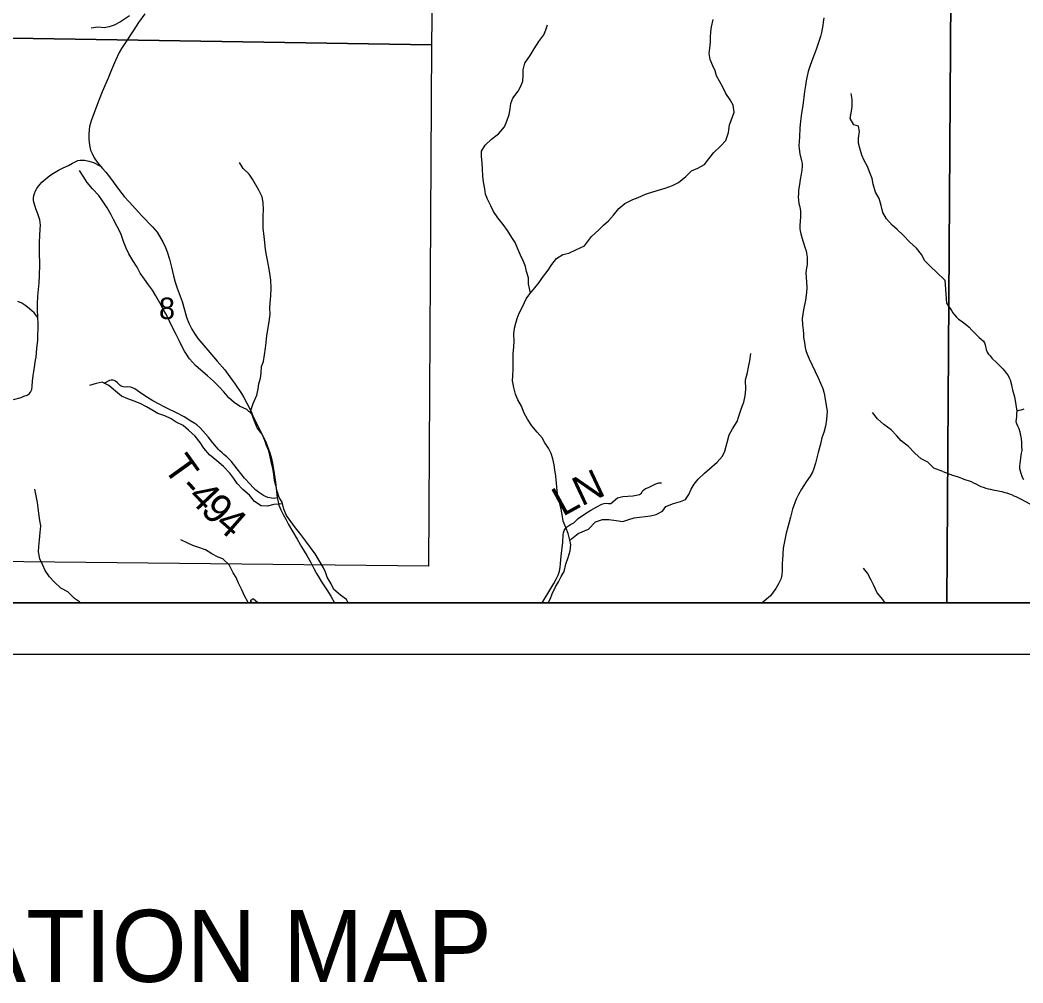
# Model space of a CAD drawing. Extents: x 0 to 34, y -8.9 to 22.
# Drawn here: x 26.904 to 28.852, y 6.366 to 8.236 of the extents above; entities that cross this region are included whole.
import ezdxf

# ---------------------------------------------------------------- set-up
doc = ezdxf.new("R2010")
doc.units = 0
for name, color, linetype in [('GM_X_Corporation', 7, 'Continuous'), ('GM_X_County_Road', 7, 'Continuous'), ('GM_X_Minor_River', 7, 'Continuous'), ('GM_X_Section_Text', 7, 'Continuous'), ('GM_X_Township_Road', 7, 'Continuous'), ('GM_X_Township_Road_Text', 7, 'Continuous'), ('SH_Data', 7, 'Continuous'), ('SH_Text', 7, 'Continuous')]:
    doc.layers.add(name, color=color, linetype=linetype)

msp = doc.modelspace()

# ---------------------------------------------------------------- linework, layer by layer
at = {"layer": 'GM_X_Corporation'}
for points in [[(28.7046, 7.104), (30.5167, 7.104), (30.5167, 13.904), (28.8143, 13.904), (28.8122, 13.7561), (28.8049, 13.053), (28.7787, 12.0377), (28.7786, 12.0342), (28.7779, 11.9899), (28.7762, 11.8872), (28.7797, 11.7437), (28.7775, 11.7346), (28.7754, 11.6346), (28.7651, 11.3014), (28.7622, 11.1187), (28.7609, 11.0119), (28.7377, 10.2012), (28.7308, 9.4444), (28.7238, 9.1729), (28.7123, 8.2818)], [(28.7046, 7.104), (30.5167, 7.104), (30.5167, 12.0118), (29.364, 12.0313), (29.2718, 12.0324), (28.9225, 12.0359), (28.8128, 12.0371), (28.7787, 12.0377), (28.7786, 12.0342), (28.7779, 11.9899), (28.7762, 11.8872), (28.7797, 11.7437), (28.7775, 11.7346), (28.7754, 11.6346), (28.7651, 11.3014), (28.7622, 11.1187), (28.7609, 11.0119), (28.7377, 10.2012), (28.7308, 9.4444), (28.7238, 9.1729), (28.7123, 8.2818)], [(27.7161, 9.2151), (27.7031, 8.1879), (26.6846, 8.2041), (26.7025, 9.2378)], [(26.6846, 8.2041), (27.7031, 8.1879), (27.6975, 7.1757), (26.6684, 7.1864)]]:
    msp.add_lwpolyline(points, close=True, dxfattribs=at)
for points in [[(23.7167, 11.9654), (23.7167, 7.104), (28.7046, 7.104), (28.7123, 8.2818), (28.7238, 9.1729), (28.7308, 9.4444), (28.7377, 10.2012)], [(24.1844, 10.755), (24.1596, 9.2636), (24.0743, 9.2644), (23.7167, 9.2682), (23.7167, 7.104), (28.7046, 7.104), (28.7123, 8.2818), (28.7238, 9.1729), (28.7308, 9.4444), (28.7377, 10.2012)]]:
    msp.add_lwpolyline(points, dxfattribs=at)
at = {"layer": 'GM_X_County_Road'}
for points in [[(27.1466, 8.2479), (27.1339, 8.2311), (27.1249, 8.2171), (27.1072, 8.1902), (27.1011, 8.1806), (27.0967, 8.1727), (27.0892, 8.1574), (27.0814, 8.1396), (27.075, 8.1233), (27.0637, 8.0969), (27.0578, 8.0819), (27.0427, 8.0422), (27.0405, 8.0358), (27.0389, 8.0296), (27.0379, 8.0229), (27.0374, 8.0145), (27.0373, 8.0044), (27.0388, 7.993), (27.0409, 7.9835), (27.0438, 7.9767), (27.0478, 7.9683), (27.0536, 7.9602), (27.0602, 7.9523)], [(27.0602, 7.9523), (27.0643, 7.9477), (27.0708, 7.9404), (27.078, 7.9316), (27.0974, 7.905), (27.1064, 7.8933), (27.1159, 7.8829), (27.1408, 7.8558), (27.1614, 7.8345), (27.1702, 7.8238), (27.1776, 7.8121), (27.1812, 7.805), (27.1864, 7.7946), (27.1899, 7.7857), (27.1944, 7.7715), (27.1981, 7.7558), (27.2018, 7.7396), (27.2056, 7.7269), (27.2093, 7.7155), (27.219, 7.6893), (27.2235, 7.6735), (27.2274, 7.6589), (27.2318, 7.6476), (27.2379, 7.6357), (27.244, 7.6251), (27.2495, 7.6175), (27.2687, 7.5946), (27.2869, 7.5736), (27.3021, 7.5564), (27.3117, 7.5433), (27.3219, 7.5288), (27.3339, 7.511), (27.3387, 7.5029), (27.3446, 7.4918), (27.3527, 7.4758), (27.3575, 7.4643), (27.3764, 7.4272), (27.3821, 7.4152), (27.3849, 7.4078), (27.3892, 7.3956), (27.3922, 7.3848), (27.3945, 7.3752), (27.3979, 7.3554), (27.4002, 7.3386), (27.4015, 7.3261), (27.4023, 7.3197), (27.4028, 7.3155), (27.4036, 7.3079), (27.4051, 7.3006), (27.407, 7.2942), (27.4107, 7.285), (27.4152, 7.2758), (27.4203, 7.2664), (27.4258, 7.2566), (27.4423, 7.2279), (27.4508, 7.2132), (27.461, 7.1961), (27.4689, 7.1824), (27.4748, 7.1712), (27.48, 7.161), (27.4852, 7.1525), (27.4899, 7.1451), (27.5002, 7.1294), (27.5079, 7.1173), (27.5151, 7.104)]]:
    msp.add_lwpolyline(points, dxfattribs=at)
at = {"layer": 'GM_X_Minor_River'}
for points in [[(27.1164, 8.2441), (27.0993, 8.2323), (27.0868, 8.2262), (27.077, 8.2231), (27.0671, 8.2212), (27.055, 8.2223), (27.0421, 8.2203)], [(27.8956, 7.7053), (27.892, 7.7239), (27.8916, 7.7357), (27.8878, 7.7478), (27.8862, 7.7573), (27.8824, 7.7668), (27.8763, 7.7796), (27.8706, 7.7929), (27.8656, 7.8039), (27.8592, 7.8138), (27.8512, 7.827), (27.8424, 7.8391), (27.8321, 7.852), (27.8241, 7.8645), (27.8184, 7.8755), (27.8119, 7.888), (27.8085, 7.8979), (27.807, 7.9081), (27.8043, 7.9221), (27.8031, 7.9328), (27.8023, 7.9472), (27.8019, 7.9578), (27.8004, 7.9719), (27.8007, 7.9813), (27.8075, 7.9931), (27.82, 8.0046), (27.8337, 8.0152), (27.845, 8.0289), (27.8499, 8.0396), (27.8541, 8.0525), (27.8563, 8.0639), (27.8578, 8.0738), (27.8612, 8.0844), (27.8718, 8.0981), (27.8767, 8.1076), (27.8805, 8.1171), (27.8816, 8.1285), (27.8812, 8.1395), (27.8846, 8.1524), (27.8948, 8.1669), (27.9031, 8.1802), (27.9118, 8.1943), (27.9213, 8.2072), (27.9254, 8.2171), (27.9285, 8.2266)], [(28.0005, 7.7978), (28.0145, 7.8159), (28.0276, 7.8278), (28.0377, 7.8374), (28.0474, 7.8462), (28.0571, 7.8574), (28.0675, 7.87), (28.0788, 7.8796), (28.0942, 7.8874), (28.1051, 7.8913), (28.119, 7.8979), (28.1333, 7.9027), (28.1465, 7.9062), (28.1571, 7.9094), (28.1718, 7.9145), (28.1834, 7.9207), (28.1973, 7.9319), (28.2085, 7.943), (28.2209, 7.9481), (28.234, 7.9555), (28.2422, 7.9666), (28.2519, 7.9788), (28.2654, 7.9915), (28.2754, 8.0023), (28.2802, 8.0175), (28.2823, 8.0323), (28.2874, 8.0464), (28.2914, 8.057), (28.2897, 8.071), (28.2835, 8.0812), (28.2755, 8.0936), (28.27, 8.1041), (28.2627, 8.1173), (28.2573, 8.1275), (28.2545, 8.1373), (28.2498, 8.1471), (28.2448, 8.1596), (28.2431, 8.1713), (28.2441, 8.1815), (28.2455, 8.1929), (28.2454, 8.2028), (28.246, 8.2134), (28.2474, 8.2229), (28.2506, 8.237)], [(28.7008, 7.7309), (28.6848, 7.7466), (28.6729, 7.7575), (28.6618, 7.7687), (28.6556, 7.7807), (28.6457, 7.7927), (28.6323, 7.8051), (28.62, 7.8182), (28.6078, 7.829), (28.5982, 7.8376), (28.5875, 7.85), (28.5801, 7.862), (28.5769, 7.876), (28.5734, 7.8896), (28.566, 7.9017), (28.5617, 7.9172), (28.5593, 7.9281), (28.5557, 7.9379), (28.5503, 7.9519), (28.5437, 7.9632), (28.5394, 7.9737), (28.5355, 7.9873), (28.5331, 7.9972), (28.533, 8.0066), (28.5351, 8.0199), (28.5331, 8.0297), (28.5236, 8.0327), (28.517, 8.0451), (28.5191, 8.0588), (28.5205, 8.0683), (28.5207, 8.0815), (28.5187, 8.0936)], [(27.351, 7.4738), (27.3571, 7.4914), (27.3639, 7.5074), (27.3665, 7.5199), (27.368, 7.5294), (27.3714, 7.5408), (27.3721, 7.5503), (27.3729, 7.5632), (27.3766, 7.5731), (27.3789, 7.586), (27.3811, 7.5985), (27.3823, 7.6095), (27.3837, 7.6232), (27.3882, 7.6498), (27.3897, 7.665), (27.3893, 7.6764), (27.3901, 7.6859), (27.3912, 7.7007), (27.3915, 7.7155), (27.3911, 7.731), (27.3892, 7.7443), (27.3865, 7.7591), (27.3846, 7.7694), (27.383, 7.7792), (27.3807, 7.7906), (27.3792, 7.8043), (27.3784, 7.8156), (27.3761, 7.8316), (27.3761, 7.8414), (27.3764, 7.8559), (27.3771, 7.8676), (27.376, 7.8817), (27.3744, 7.8927), (27.3679, 7.9059), (27.3554, 7.9268), (27.3493, 7.937), (27.3375, 7.9476), (27.3303, 7.9597)], [(27.1155, 7.7818), (27.1102, 7.7928), (27.1052, 7.806), (27.0995, 7.8212), (27.0926, 7.8352), (27.0854, 7.8485), (27.0808, 7.858), (27.0732, 7.8716), (27.0644, 7.8849), (27.0568, 7.8951), (27.0446, 7.9083), (27.034, 7.9204), (27.0268, 7.9326), (27.0191, 7.9439)], [(27.9299, 7.104), (27.9347, 7.1125), (27.9377, 7.122), (27.9441, 7.1353), (27.9502, 7.1449), (27.9551, 7.1555), (27.9611, 7.165), (27.9641, 7.1791), (27.9687, 7.1924), (27.9728, 7.2053), (27.9739, 7.2167), (27.972, 7.2262), (27.9686, 7.2387), (27.9644, 7.2504), (27.9594, 7.2629), (27.9575, 7.2758), (27.9544, 7.2895), (27.9521, 7.299), (27.9494, 7.3084), (27.9475, 7.3217), (27.9463, 7.3365), (27.9452, 7.3502), (27.9432, 7.3627), (27.9417, 7.3722), (27.939, 7.3839), (27.9356, 7.3942), (27.9306, 7.4044), (27.9238, 7.415), (27.9181, 7.4245), (27.9086, 7.4359), (27.8983, 7.448), (27.8899, 7.4612), (27.8834, 7.4726), (27.8781, 7.4862), (27.8712, 7.4987), (27.8667, 7.5097), (27.8632, 7.5226), (27.8609, 7.5352), (27.8613, 7.545), (27.862, 7.5579), (27.862, 7.5735), (27.8623, 7.5879), (27.863, 7.6016), (27.8638, 7.6126), (27.8634, 7.6266), (27.8645, 7.6376), (27.8675, 7.6471), (27.8697, 7.6566), (27.8735, 7.6665), (27.8811, 7.6802), (27.8875, 7.6943), (27.8947, 7.7042), (27.9041, 7.716), (27.9125, 7.7266), (27.9189, 7.7361), (27.9303, 7.7502), (27.9374, 7.7612), (27.9465, 7.7727), (27.9583, 7.7807), (27.9704, 7.783), (27.9837, 7.7899), (28.0005, 7.7978)], [(27.5414, 7.104), (27.5385, 7.1105), (27.5268, 7.1192), (27.5138, 7.1298), (27.5081, 7.1412), (27.5005, 7.154), (27.4974, 7.1639), (27.4929, 7.1734), (27.4853, 7.1863), (27.4776, 7.1995), (27.4685, 7.212), (27.4594, 7.2238), (27.4495, 7.237), (27.4392, 7.2499), (27.4217, 7.2741), (27.4164, 7.2862), (27.4129, 7.2995), (27.4076, 7.309), (27.4041, 7.3192), (27.4011, 7.3321), (27.3984, 7.342), (27.3972, 7.3534), (27.3953, 7.3648), (27.3919, 7.3784), (27.3899, 7.3879), (27.3873, 7.3993), (27.3827, 7.4095), (27.3793, 7.4194), (27.3743, 7.4319), (27.3648, 7.4444), (27.3594, 7.4569), (27.3545, 7.4705), (27.3446, 7.48), (27.3302, 7.4864), (27.3199, 7.4932), (27.3096, 7.5023), (27.2997, 7.514), (27.2902, 7.5242), (27.2796, 7.5348), (27.2678, 7.545), (27.2553, 7.556), (27.245, 7.5651), (27.2332, 7.5783), (27.2233, 7.5927), (27.2183, 7.6026), (27.213, 7.6139), (27.2077, 7.6242), (27.2016, 7.6363), (27.1943, 7.6515), (27.1875, 7.6647), (27.1821, 7.6742), (27.1757, 7.6871), (27.1677, 7.7007), (27.1612, 7.7117), (27.1536, 7.7219), (27.1456, 7.7329), (27.1376, 7.7446), (27.1315, 7.756), (27.1231, 7.7693), (27.1155, 7.7818)], [(28.7008, 7.7309), (28.7037, 7.6865), (28.7137, 7.6718), (28.7164, 7.6673), (28.7195, 7.6636), (28.7233, 7.6587), (28.7272, 7.655), (28.7322, 7.6517), (28.7375, 7.648), (28.7433, 7.6436), (28.7483, 7.6399), (28.7529, 7.6339), (28.7579, 7.629), (28.7629, 7.6238), (28.7675, 7.6197), (28.7714, 7.6164), (28.776, 7.6127), (28.7779, 7.6089), (28.7788, 7.6051), (28.7812, 7.5961), (28.7832, 7.5912), (28.7855, 7.5874), (28.7886, 7.5837), (28.7921, 7.5796), (28.8017, 7.5703), (28.8059, 7.5666), (28.8098, 7.5628), (28.8136, 7.5584), (28.8167, 7.5546), (28.8206, 7.5494), (28.8237, 7.5457), (28.826, 7.5415), (28.8276, 7.5374), (28.8301, 7.5276), (28.8309, 7.523), (28.8325, 7.5181), (28.8337, 7.5132), (28.8349, 7.5091), (28.8358, 7.5045), (28.8366, 7.5008), (28.8404, 7.4766)], [(28.0081, 7.2474), (28.0221, 7.2618), (28.0353, 7.2658), (28.0477, 7.2663), (28.0621, 7.2642), (28.0754, 7.2625), (28.0867, 7.266), (28.0972, 7.2692), (28.1074, 7.2705), (28.1184, 7.2717), (28.129, 7.273), (28.1399, 7.2758), (28.1523, 7.282), (28.1586, 7.2916), (28.1737, 7.2971), (28.1869, 7.3007), (28.197, 7.305), (28.2033, 7.3145), (28.2081, 7.3248), (28.2137, 7.3347), (28.2215, 7.3447), (28.2339, 7.3558), (28.2436, 7.3643), (28.2582, 7.3774), (28.269, 7.3889), (28.2734, 7.3988), (28.2781, 7.4159), (28.2817, 7.4303), (28.2884, 7.4422), (28.2973, 7.4567), (28.3006, 7.467), (28.3064, 7.4841), (28.3104, 7.494), (28.3126, 7.5062), (28.3139, 7.5183), (28.3137, 7.5373), (28.3173, 7.5513), (28.3194, 7.562), (28.3216, 7.5741), (28.3237, 7.5882)], [(27.4136, 7.2968), (27.397, 7.2949), (27.3848, 7.2918), (27.3723, 7.2926), (27.3594, 7.3009), (27.3495, 7.313), (27.3366, 7.324), (27.3259, 7.3357), (27.3191, 7.3459), (27.3115, 7.3561), (27.2989, 7.369), (27.2864, 7.3803), (27.2719, 7.3917), (27.2613, 7.4046), (27.254, 7.4155), (27.2442, 7.428), (27.2312, 7.4394), (27.221, 7.4485), (27.2073, 7.4553), (27.1974, 7.4617), (27.1849, 7.4677), (27.1716, 7.4722), (27.1617, 7.4775), (27.1499, 7.4847), (27.1374, 7.4911), (27.1256, 7.4956), (27.1135, 7.5001), (27.1009, 7.5054), (27.0891, 7.5152), (27.0766, 7.5262), (27.0637, 7.5326), (27.0519, 7.5303), (27.039, 7.5261)], [(28.6968, 7.3594), (28.6793, 7.366), (28.6678, 7.3776), (28.6545, 7.3839), (28.6426, 7.3951), (28.63, 7.4078), (28.6158, 7.419), (28.6074, 7.4288), (28.5967, 7.4404), (28.5822, 7.4504), (28.5699, 7.4613), (28.5599, 7.474)], [(28.854, 7.4802), (28.8483, 7.4786), (28.8442, 7.4778), (28.8404, 7.4766), (28.8401, 7.4716), (28.8402, 7.4663), (28.8395, 7.461), (28.8389, 7.4561), (28.8397, 7.4523), (28.842, 7.4482), (28.8444, 7.4425), (28.8464, 7.4361), (28.8472, 7.432), (28.8481, 7.4271), (28.8489, 7.4221), (28.8494, 7.4165), (28.8495, 7.4123), (28.8499, 7.4085), (28.8501, 7.3998), (28.849, 7.3948), (28.8487, 7.3903), (28.848, 7.3857), (28.847, 7.3796), (28.8467, 7.3751), (28.846, 7.3698), (28.8461, 7.3648), (28.847, 7.3603), (28.8482, 7.3562), (28.8494, 7.352), (28.8513, 7.3483), (28.8533, 7.3437)], [(28.6968, 7.3594), (28.7154, 7.3519), (28.7204, 7.3509), (28.7265, 7.3487), (28.7333, 7.3462), (28.7375, 7.3447), (28.7417, 7.3429), (28.7462, 7.3419), (28.752, 7.3397), (28.7562, 7.3375), (28.7611, 7.3353), (28.7665, 7.332), (28.7707, 7.3302), (28.7752, 7.3287), (28.7806, 7.3269), (28.7847, 7.3255), (28.7897, 7.3248), (28.7942, 7.3234), (28.798, 7.3231), (28.8018, 7.3224), (28.8079, 7.321), (28.8117, 7.3203), (28.8174, 7.3185), (28.8212, 7.3178), (28.8258, 7.316), (28.83, 7.3145), (28.8345, 7.3123), (28.8387, 7.3105), (28.8425, 7.3091), (28.8467, 7.3069), (28.8673, 7.2957)], [(27.0211, 7.104), (27.0195, 7.1062), (27.0096, 7.1126), (26.997, 7.1255), (26.9834, 7.133), (26.9701, 7.1448), (26.9609, 7.155), (26.9529, 7.1671), (26.9483, 7.1773), (26.9426, 7.1898), (26.9396, 7.2031), (26.9403, 7.2137), (26.9414, 7.2267), (26.9429, 7.2407), (26.944, 7.2536), (26.9421, 7.2642), (26.9405, 7.2775), (26.939, 7.2889), (26.9375, 7.2991), (26.9352, 7.3117), (26.9325, 7.3249)], [(27.9722, 7.2254), (27.9754, 7.2284), (27.9883, 7.2391), (28.0081, 7.2474)], [(27.3478, 7.104), (27.3473, 7.1046), (27.3397, 7.1175), (27.3347, 7.1296), (27.3283, 7.1425), (27.3237, 7.1531), (27.318, 7.1626), (27.31, 7.1777), (27.2982, 7.1895), (27.2887, 7.1932), (27.2765, 7.1993), (27.264, 7.2072), (27.2496, 7.2121), (27.2397, 7.2158), (27.2298, 7.2204), (27.2165, 7.2268)], [(28.5847, 7.104), (28.5803, 7.1104), (28.5695, 7.1239), (28.5629, 7.1382), (28.5579, 7.148), (28.5506, 7.1616), (28.5425, 7.1713)]]:
    msp.add_lwpolyline(points, dxfattribs=at)
at = {"layer": 'GM_X_Township_Road'}
for points in [[(28.4659, 8.2404), (28.4642, 8.2322), (28.4635, 8.2253), (28.4609, 8.2119), (28.459, 8.2042), (28.4549, 8.1906), (28.4517, 8.1807), (28.4488, 8.1736), (28.444, 8.1618), (28.4389, 8.148), (28.4352, 8.1358), (28.4325, 8.1244), (28.4313, 8.1178), (28.4297, 8.1091), (28.428, 8.0974), (28.4247, 8.0701), (28.4223, 8.0549), (28.4203, 8.0399), (28.4192, 8.0259), (28.4181, 8.009), (28.4175, 7.9999), (28.4173, 7.9925), (28.4174, 7.9857), (28.4187, 7.9763), (28.4221, 7.9629), (28.4235, 7.9573), (28.4237, 7.9524), (28.4229, 7.9445), (28.4216, 7.9368), (28.4198, 7.9265), (28.4181, 7.9166), (28.4167, 7.9054), (28.4161, 7.8978), (28.416, 7.8935), (28.4165, 7.8859), (28.4171, 7.8798), (28.4187, 7.8735), (28.4196, 7.8691), (28.4201, 7.865), (28.4203, 7.8592), (28.4202, 7.8536), (28.4187, 7.8369), (28.419, 7.8307), (28.4197, 7.8264), (28.4209, 7.8206), (28.4228, 7.8137), (28.4256, 7.8053), (28.4294, 7.7933), (28.431, 7.788), (28.432, 7.7833), (28.433, 7.7758), (28.4333, 7.7672), (28.433, 7.7604), (28.432, 7.7551), (28.4309, 7.7448), (28.431, 7.7359), (28.4317, 7.7279), (28.4323, 7.7165), (28.4319, 7.707), (28.4303, 7.692), (28.4264, 7.6733), (28.4247, 7.6646), (28.4238, 7.6563), (28.4243, 7.6443), (28.4253, 7.6337), (28.4258, 7.6265), (28.4263, 7.6198), (28.4278, 7.6099), (28.4293, 7.6002), (28.4309, 7.594), (28.4334, 7.5874), (28.4373, 7.5779), (28.443, 7.5655), (28.4549, 7.5411), (28.4635, 7.5205), (28.4658, 7.5134), (28.467, 7.5073), (28.4682, 7.4992), (28.4719, 7.4765), (28.4709, 7.4601), (28.4691, 7.4473), (28.4658, 7.4353), (28.462, 7.4244), (28.4591, 7.4121), (28.4549, 7.3964), (28.4494, 7.3755), (28.4453, 7.3633), (28.4434, 7.358), (28.4393, 7.3504), (28.4314, 7.339), (28.4223, 7.3251), (28.4162, 7.3147), (28.4118, 7.3055), (28.4048, 7.2863), (28.4007, 7.2708), (28.396, 7.251), (28.3925, 7.2394), (28.3869, 7.2101), (28.3854, 7.1879), (28.3849, 7.1813), (28.3848, 7.1674), (28.3839, 7.1589), (28.3832, 7.1551), (28.3818, 7.1501), (28.3778, 7.1409), (28.3726, 7.132), (28.3621, 7.1179), (28.3457, 7.104)], [(26.8909, 7.4992), (26.9059, 7.5033), (26.9115, 7.5053), (26.918, 7.5075), (26.9217, 7.5099), (26.9243, 7.5132), (26.9265, 7.5185), (26.9275, 7.5253), (26.9281, 7.5344), (26.9295, 7.5456), (26.9304, 7.5537), (26.9318, 7.5622), (26.9342, 7.5757), (26.9351, 7.5813), (26.9365, 7.5982), (26.9384, 7.6142), (26.9394, 7.6468), (26.9387, 7.6586), (26.9379, 7.6736), (26.9377, 7.6844), (26.9383, 7.6999), (26.9409, 7.7258), (26.9417, 7.739), (26.9421, 7.7612), (26.9416, 7.7853), (26.942, 7.8042), (26.9423, 7.8177), (26.9428, 7.8302), (26.9434, 7.8378), (26.943, 7.8427), (26.9424, 7.848), (26.9406, 7.8541), (26.9386, 7.8595), (26.9347, 7.8692), (26.933, 7.8742), (26.9307, 7.8822), (26.9303, 7.8867), (26.9303, 7.8913), (26.9308, 7.8948), (26.9317, 7.8992), (26.9339, 7.9044), (26.9363, 7.9086), (26.9398, 7.9136), (26.9465, 7.9212), (26.954, 7.9278), (26.9619, 7.9341), (26.969, 7.9388), (26.9783, 7.9444), (26.988, 7.9492), (26.9978, 7.9537), (27.0059, 7.9582), (27.0121, 7.9614), (27.0161, 7.963), (27.0205, 7.9639), (27.0242, 7.9641), (27.0289, 7.9636), (27.0374, 7.9619), (27.0421, 7.9607), (27.0463, 7.9591), (27.0602, 7.9523)], [(26.9387, 7.6586), (26.9312, 7.6674), (26.9223, 7.6754), (26.9149, 7.6813), (26.9071, 7.686), (26.8999, 7.6894)], [(27.4036, 7.3079), (27.3978, 7.307), (27.3922, 7.3074), (27.3854, 7.309), (27.3807, 7.3109), (27.3767, 7.3129), (27.3674, 7.3189), (27.3616, 7.3238), (27.3564, 7.3288), (27.3507, 7.3347), (27.34, 7.3466), (27.3255, 7.3645), (27.3143, 7.3795), (27.3058, 7.3879), (27.3001, 7.3926), (27.2965, 7.3955), (27.2922, 7.3994), (27.2896, 7.402), (27.2856, 7.4065), (27.2787, 7.4148), (27.2692, 7.4268), (27.2538, 7.444), (27.2471, 7.4501), (27.2437, 7.4525), (27.2358, 7.4572), (27.2227, 7.4652), (27.208, 7.4731), (27.1894, 7.4823), (27.1827, 7.4854), (27.1756, 7.4894), (27.162, 7.4967), (27.1517, 7.5027), (27.1444, 7.5074), (27.1358, 7.5136), (27.1269, 7.5201), (27.1193, 7.5231), (27.1135, 7.5238), (27.1088, 7.523), (27.1042, 7.5234), (27.1005, 7.5248), (27.0982, 7.5265), (27.0962, 7.5285), (27.0933, 7.5314), (27.0894, 7.5344), (27.0868, 7.5358), (27.0841, 7.5365), (27.0808, 7.5366), (27.0777, 7.5357), (27.0665, 7.5303)], [(27.9183, 7.104), (27.9354, 7.1319), (27.941, 7.1419), (27.9463, 7.1517), (27.9493, 7.1577), (27.9508, 7.1617), (27.9519, 7.1658), (27.9536, 7.1731), (27.9543, 7.1804), (27.9553, 7.195), (27.9584, 7.222), (27.959, 7.236), (27.9595, 7.2403), (27.9608, 7.2445), (27.9635, 7.2487), (27.9659, 7.2513), (27.9733, 7.2561), (27.9799, 7.2596), (27.9824, 7.262), (27.9885, 7.2681), (28.0026, 7.2779), (28.0131, 7.2844), (28.0247, 7.2908), (28.0345, 7.2957), (28.0389, 7.2973), (28.0428, 7.298), (28.0473, 7.2973), (28.052, 7.2969), (28.0645, 7.3079), (28.0696, 7.3097), (28.0748, 7.3106), (28.0946, 7.312), (28.1074, 7.3149), (28.1111, 7.317), (28.1125, 7.3204), (28.1158, 7.3239), (28.1192, 7.3261), (28.1252, 7.3282), (28.1392, 7.3353), (28.1449, 7.3372), (28.1503, 7.3375)], [(27.3573, 7.104), (27.3554, 7.1044), (27.3536, 7.1053), (27.3525, 7.1072), (27.3523, 7.1091), (27.354, 7.1108), (27.3555, 7.1119), (27.3577, 7.1118), (27.3611, 7.1089), (27.3665, 7.104)]]:
    msp.add_lwpolyline(points, dxfattribs=at)
at = {"layer": 'SH_Data'}
for points in [[(23.6167, 14.004), (30.6167, 14.004), (30.6167, 7.004), (23.6167, 7.004)], [(23.7167, 13.904), (30.5167, 13.904), (30.5167, 7.104), (23.7167, 7.104)]]:
    msp.add_lwpolyline(points, close=True, dxfattribs=at)

# ---------------------------------------------------------------- texts
at = {"layer": 'GM_X_Section_Text'}
msp.add_text('8', height=0.0419, rotation=0, dxfattribs=at).set_placement((27.1738, 7.6552))
at = {"layer": 'GM_X_Township_Road_Text'}
for s, rotation, p in [('T', 305.6338, (27.181, 7.3665)), ('N', 25.1883, (27.9948, 7.2912)), ('-', 314.0172, (27.2115, 7.325)), ('4', 313.6016, (27.2277, 7.3083)), ('L', 28.8157, (27.9584, 7.2711)), ('9', 314.6147, (27.2526, 7.2822)), ('4', 318.7621, (27.2804, 7.2542))]:
    msp.add_text(s, height=0.0568, rotation=rotation, dxfattribs=at).set_placement(p)
at = {"layer": 'SH_Text'}
msp.add_text('LOCATION MAP', height=0.14, dxfattribs=at).set_placement((26.4057, 6.368))

doc.saveas('drawing.dxf')
